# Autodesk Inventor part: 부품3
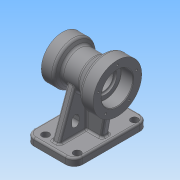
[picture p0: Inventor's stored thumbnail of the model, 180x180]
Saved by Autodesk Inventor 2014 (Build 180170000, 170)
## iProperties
Created: 2015-08
Part Number: 부품3
Material: 일반
Document SubType Name: Modeling
Designer: net
Density: 1 g/cm^3
Appearance: 기본값
Author: net
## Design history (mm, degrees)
sketch "스케치1"
  geometry: L1 (-25, 35)-(-19.804, 26); L2 (-19.804, 26)-(8.315, 26); L3 (8.315, 26)-(25, 40); L4 (-25, -35)-(-45, -35); L5 (-45, -35)-(-45, 35); L6 (8.315, -26)-(-19.804, -26); L7 (-19.804, -26)-(-25, -35); L8 (25, -40)-(8.315, -26); L9 (45, -40)-(25, -40); L10 (45, 40)-(45, -40); L11 (25, 40)-(45, 40); L12 (-45, 35)-(-25, 35); L13 (-45, 0)-(45, 0); 1 further point
  constraints: 26 end point, 5 horizontal, 4 equal length, 2 midpoint, 2 vertical, 1 parallel
  dimensions: "d0" = 140 deg angle of L2 L3; "d1" = 140 deg angle of L8 L6; "d2" = 70 distance between parallel lines of L4 L12; "d3" = 120 deg angle of L2 L1; "d4" = 120 deg angle of L6 L7; "d5" = 80 distance of L10.start L9.start; "d6" = 20 distance of L3.end L10.start; "d7" = 20 distance of L5.end L1.start; "d8" = 90 distance between parallel lines of L10 L5; "d9" = 52 distance between parallel lines of L2 L6; "d10" = 26 distance from line of point (0, 0) L2; "d11" = 45 distance from line of point (0, 0) L5
revolve "회전1" sketch "스케치1" stored, may be unused: angle "d12" = 90 deg
sketch "스케치2"
  geometry: C1 r 40 at (0, 0) reference; C2 r 16 at (0, 0)
  constraints: 1 centre point, 1 coincident
  dimensions: "d13" = 32 diameter of C2
extrude "돌출1" cut sketch "스케치2" stored distance "d14" = 10; taper "d15" = 0 deg
sketch "스케치3"
  geometry: C1 r 16 at (0, 0) reference; C2 r 40 at (0, 0) reference; C3 r 26 at (0, 0)
  constraints: 1 centre point, 1 coincident
  dimensions: "d16" = 52 diameter of C3
extrude "돌출2" cut sketch "스케치3" distance "d17" = 20; taper "d18" = 0 deg
sketch "스케치4"
  geometry: C1 r 16 at (0, 0) reference; C2 r 26 at (0, 0) reference; C3 r 19 at (0, 0)
  constraints: 1 centre point, 1 coincident
  dimensions: "d19" = 38 diameter of C3
extrude "돌출3" cut sketch "스케치4" distance "d20" = 3; taper "d21" = 0 deg
sketch "스케치5"
  geometry: C1 r 16 at (0, 0) reference; C2 r 35 at (0, 0) reference; C3 r 20 at (0, 0)
  constraints: 1 centre point, 1 coincident
  dimensions: "d22" = 40 diameter of C3
extrude "돌출4" cut sketch "스케치5" distance "d23" = 17; taper "d24" = 0 deg
node "작업 평면1"
sketch "스케치6"
  geometry: L1 (-45, -61)-(35, -61); L2 (35, -61)-(35, 61); L3 (35, 61)-(-45, 61); L4 (-45, 61)-(-45, -61); 1 further point
  constraints: 8 end point, 2 parallel, 1 horizontal, 1 perpendicular
  dimensions: "d26" = 122 distance of L3.end L1.start; "d27" = 80 distance of L1.start L1.end; "d28" = 45 distance from line of point (0, 0) L4; "d29" = 61 distance from line of point (0, 0) L1
extrude "돌출5" join sketch "스케치6" distance "d30" = 12; taper "d31" = 0 deg
sketch "스케치8"
  geometry: L1 (45, -78)-(-35, -78) reference; L2 (19.804, 26)-(19.804, -26) reference; L3 (35, -78)-(81.604, -78); L4 (-25, -78)-(-2.81, -78); L5 (-25, -78)-(-33.302, -30.916); L6 (-25, -78)-(22.811, -78); L7 (-33.302, -30.916)-(15.831, -22.252); L8 (15.831, -22.252)-(35, -27.986); L9 (35, -78)-(35, -27.986); 1 further point
  constraints: 14 end point, 3 horizontal, 2 point on line, 1 equal length, 1 perpendicular, 1 vertical
  dimensions: "d37" = 10 distance of L1.start L3.start; "d40" = 100 deg angle of L6 L5; "d41" = 10 distance of L4.start L1.end
extrude "돌출6" join sketch "스케치8" stored distance "d42" = 12; taper "d43" = 0 deg
sketch "스케치9"
  geometry: L1 (-51, -78)-(-16.389, 17.092); L2 (-16.389, 17.092)-(16.389, 17.092); L3 (16.389, 17.092)-(51, -78); L4 (61, -90)-(-61, -90) reference; L5 (-61, -90)-(-61, -78) reference; L6 (61, -78)-(-61, -78) reference; L7 (61, -90)-(61, -78) reference; L8 (-51, -78)-(51, -78); 1 further point
  constraints: 8 end point, 1 equal length, 1 horizontal, 1 point on line
  dimensions: "d44" = 10 distance of L1.start L5.end; "d45" = 10 distance of L6.start L3.end; "d46" = 70 deg angle of L6 L1; "d47" = 70 deg angle of L6 L3
extrude "돌출7" join sketch "스케치9" distance "d49" = 12; taper "d50" = 0 deg
sketch "스케치10"
  geometry: C1 r 16 at (0, 0) reference; C2 r 16 at (0, 0)
  constraints: 1 centre point, 1 coincident, 1 concentric
extrude "돌출8" cut sketch "스케치10" stored distance "d51" = 12; taper "d52" = 0 deg
sketch "스케치11"
  geometry: C1 r 6 at (-26, 47); C2 r 6 at (26, 47); 1 further point
  constraints: 2 centre point
  dimensions: "d53" = 12 diameter of C1; "d54" = 12 diameter of C2; "d55" = 52 distance of C2.centre C1.centre; "d56" = 47 vertical distance of point (0, 0) C1.centre; "d57" = 26 horizontal distance of point (0, 0) C1.centre; "d58" = 26 horizontal distance of point (0, 0) C2.centre
extrude "돌출9" cut sketch "스케치11" stored distance "d59" = 0; taper "d60" = 0 deg
fillet "모깎기1" dims "d61" = 14
sketch "스케치12"
  geometry: L1 (54, -18)-(60, -18); L2 (60, -30)-(54, -30); L3 (90, -47)-(90, 47) reference; A1 r 26 centre (0, 0) between (6.815, -25.091) and (25.298, -6) reference; A2 r 6 centre (54, -24) between (54, -18) and (54, -30); A3 r 6 centre (60, -24) between (60, -30) and (60, -18)
  constraints: 4 end point, 4 point on circle, 4 tangent, 2 centre point, 1 horizontal
  dimensions: "d62" = 12 diameter of A2; "d63" = 12 diameter of A3; "d64" = 18 dimension on A3 A2; "d65" = 24 vertical distance of A1.centre A2.centre; "d67" = 30 distance from line of L3 A3.centre
extrude "돌출10" cut sketch "스케치12" stored distance "d68" = 0; taper "d69" = 0 deg
fillet "모깎기2" dims "d70" = 3
fillet "모깎기3" dims "d71" = 3
fillet "모깎기4" dims "d72" = 3
fillet "모깎기5" dims "d73" = 3
fillet "모깎기8" dims "d76" = 5
fillet "모깎기9" dims "d77" = 3
sketch "스케치13" dims "d78" = 66
  geometry: C1 r 40 at (0, 0) reference; 2 further points
  constraints: 2 horizontal alignment, 1 coincident, 2 other
hole "구멍1" sketch "스케치13" at (-33, 0) diameter "d79" = 3.242; stored, may be unused: countersink angle "d83" = 90 deg, drill point angle "d85" = 118 deg; dims "d80" = 10, "d81" = 4, "d82" = 2, "d84" = 13
sketch "스케치14" dims "d89" = 54
  geometry: C1 r 20 at (0, 0) reference; C2 r 35 at (0, 0) reference; 2 further points
  constraints: 2 horizontal alignment, 1 coincident, 2 other
hole "구멍2" sketch "스케치14" at (27, 0) diameter "d90" = 3.242; stored, may be unused: countersink angle "d94" = 90 deg, drill point angle "d96" = 118 deg; dims "d91" = 10, "d92" = 4, "d93" = 2, "d95" = 13
sketch "스케치15"
  geometry: L1 (-35, -37.881)-(-35, -75) reference; L2 (-42, -78)-(-31, -78) reference; 8 further points
  constraints: 1 other
  dimensions: "d100" = 16 distance from line of L1 point (-19, -54); "d101" = 24 distance from line of L2 point (-19, -54)
extrude "돌출11" join sketch "스케치15" distance "d102" = 0.5; taper "d103" = 0 deg
fillet "모깎기10" dims "d104" = 3
chamfer "모따기1" distance "d105" = 1; stored, may be unused: second distance "d106" = 2, angle "d107" = 45 deg
chamfer "모따기2" distance "d108" = 1; stored, may be unused: second distance "d109" = 2, angle "d110" = 45 deg
fillet "모깎기11" dims "d111" = 0.3
node "솔리드1"
mirror "대칭1"
mirror "대칭2"
pattern_circular "원형 패턴1" dims angle "d87" = 360 deg
pattern_circular "원형 패턴2" dims angle "d98" = 360 deg
node "투영된 루프1"
